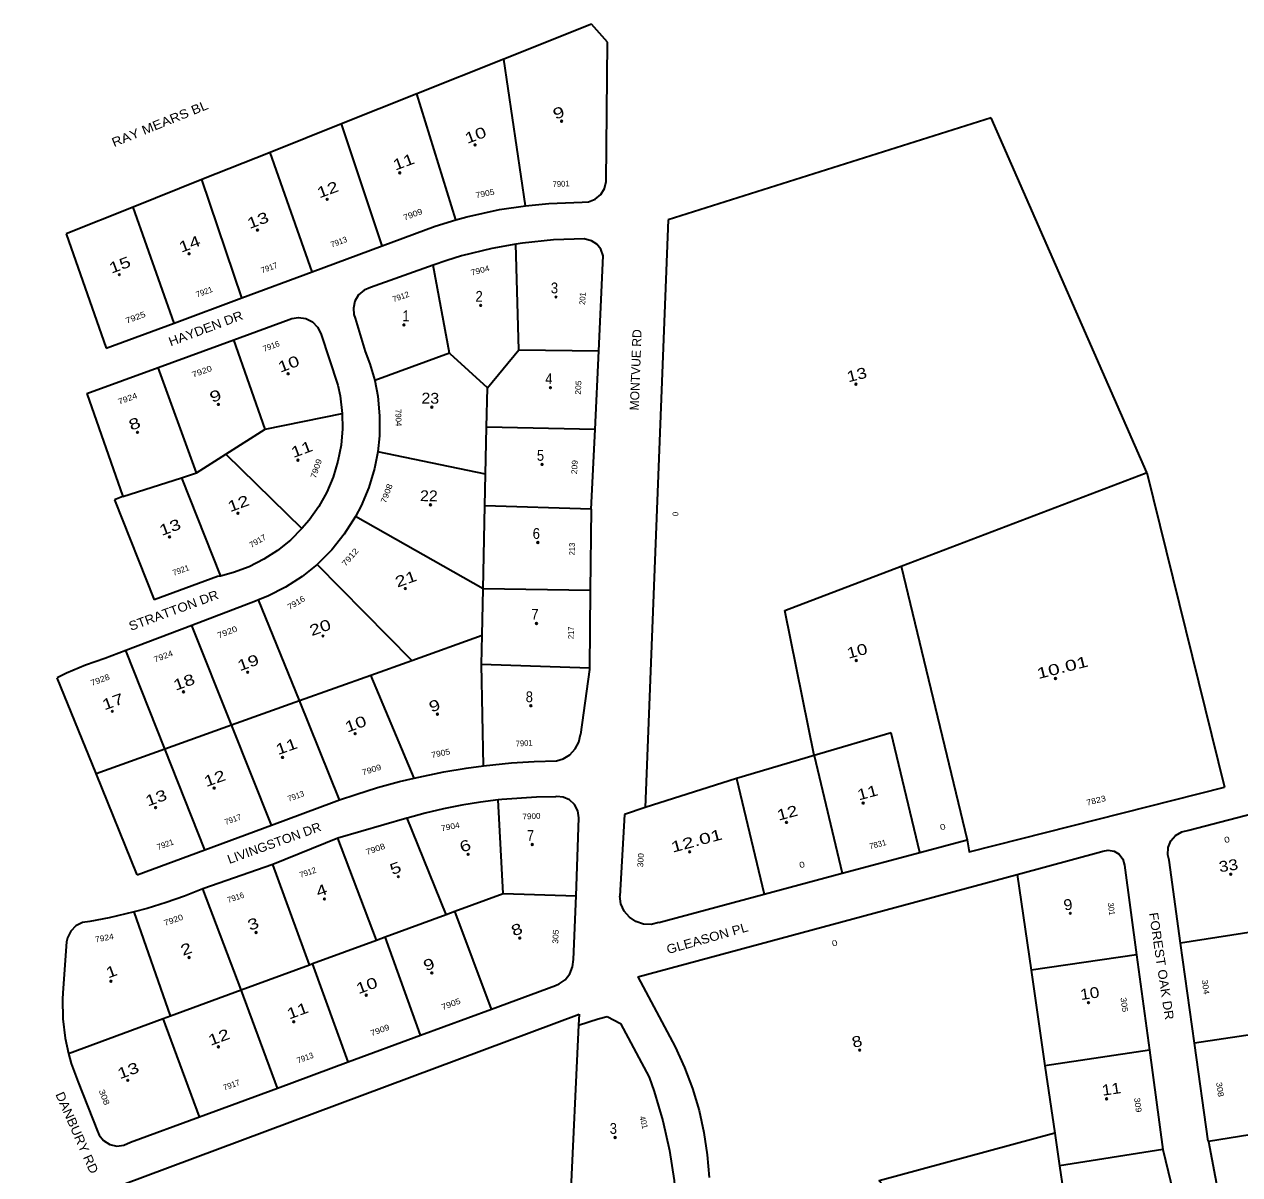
# Model space of a CAD drawing. Extents: x 2546959 to 2550387, y 581906 to 585027.
# Drawn here: x 2547419 to 2549102, y 583434 to 585027 of the extents above; entities that cross this region are included whole.
import ezdxf
from ezdxf.enums import TextEntityAlignment as Align

# ---------------------------------------------------------------- set-up
doc = ezdxf.new("R2010")
doc.units = 0
doc.header["$LTSCALE"] = 5
doc.header["$PDMODE"] = 32
doc.header["$PDSIZE"] = 2.5
for name, color, linetype in [('20', 7, 'Continuous'), ('38', 7, 'Continuous'), ('39', 7, 'Continuous'), ('41', 7, 'Continuous')]:
    doc.layers.add(name, color=color, linetype=linetype)
doc.layers.add('40', color=7, linetype='Continuous', lineweight=35)

msp = doc.modelspace()

# ---------------------------------------------------------------- linework, layer by layer
at = {"layer": '40'}
for p, q in [((2548204.014, 585026.501), (2548082.739, 584978.146)), ((2548226.245, 585001.697), (2548204.014, 585026.501)), ((2548224.277, 584808.852), (2548226.245, 585001.697)), ((2548082.739, 584978.146), (2547962.303, 584930.126)), ((2548112.924, 584775.333), (2548082.739, 584978.146)), ((2547962.303, 584930.126), (2547858.204, 584888.62)), ((2548016.151, 584755.782), (2547962.303, 584930.126)), ((2547858.204, 584888.62), (2547759.114, 584849.112)), ((2547914.388, 584719.889), (2547858.204, 584888.62)), ((2548757.466, 584896.871), (2548310.336, 584755.908)), ((2548972.954, 584405.881), (2548757.466, 584896.871)), ((2547759.114, 584849.112), (2547664.568, 584811.416)), ((2547817.297, 584683.807), (2547759.114, 584849.112)), ((2547664.568, 584811.416), (2547569.517, 584773.517)), ((2547720.206, 584647.727), (2547664.568, 584811.416)), ((2547569.517, 584773.517), (2547476.689, 584736.505)), ((2547626.39, 584612.862), (2547569.517, 584773.517)), ((2547987.542, 584747.075), (2548016.151, 584755.782)), ((2548310.336, 584755.908), (2548278.336, 583942.322)), ((2547476.689, 584736.505), (2547532.448, 584577.95)), ((2547914.388, 584719.889), (2547987.542, 584747.075)), ((2547817.297, 584683.807), (2547914.388, 584719.889)), ((2548103.512, 584576.042), (2548099.538, 584722.294)), ((2548003.755, 584699.71), (2547984.922, 584692.969)), ((2548214.27, 584574.238), (2548220.537, 584706.084)), ((2547720.206, 584647.727), (2547817.297, 584683.807)), ((2547984.922, 584692.969), (2547898.412, 584662.004)), ((2548007.585, 584570.978), (2547984.922, 584692.969)), ((2547626.39, 584612.862), (2547720.206, 584647.727)), ((2547709.072, 584589.763), (2547785.46, 584617.652)), ((2547532.448, 584577.95), (2547626.39, 584612.862)), ((2547829.533, 584598.297), (2547852.84, 584526.961)), ((2547752.252, 584465.989), (2547709.072, 584589.763)), ((2548007.585, 584570.978), (2547904.091, 584533.141)), ((2548008.322, 584570.311), (2548007.585, 584570.978)), ((2548060.181, 584523.422), (2548008.322, 584570.311)), ((2548060.181, 584523.422), (2548103.512, 584576.042)), ((2548103.512, 584576.042), (2548214.27, 584574.238)), ((2548209.112, 584465.708), (2548214.27, 584574.238)), ((2547505.384, 584515.396), (2547604.222, 584551.482)), ((2547505.384, 584515.396), (2547555.274, 584372.68)), ((2547697.97, 584431.3), (2547752.252, 584465.989)), ((2548209.112, 584465.708), (2548059.011, 584468.839)), ((2548203.861, 584355.253), (2548209.112, 584465.708)), ((2547657.54, 584405.464), (2547697.97, 584431.3)), ((2547697.97, 584431.3), (2547803.347, 584328.288)), ((2548057.619, 584403.911), (2547908.224, 584434.685)), ((2547636.483, 584398.714), (2547657.54, 584405.464)), ((2547636.483, 584398.714), (2547690.507, 584262.679)), ((2548632.906, 584276.263), (2548972.05, 584405.537)), ((2547555.553, 584372.77), (2547543.687, 584368.085)), ((2547543.687, 584368.085), (2547598.762, 584229.478)), ((2548054.214, 584245.13), (2547877.415, 584344.957)), ((2548203.861, 584355.253), (2548202.493, 584242.777)), ((2547955.225, 584145.719), (2547824.237, 584278.814)), ((2547686.611, 584261.811), (2547598.762, 584229.478)), ((2547690.507, 584262.679), (2547686.611, 584261.811)), ((2548471.7, 584214.815), (2548632.906, 584276.263)), ((2548632.906, 584276.263), (2548724.329, 583897.607)), ((2548052.831, 584180.633), (2548054.214, 584245.13)), ((2547739.134, 584227.906), (2547650.734, 584194.276)), ((2547743.36, 584229.523), (2547739.134, 584227.906)), ((2547799.804, 584090.124), (2547743.36, 584229.523)), ((2548202.493, 584242.777), (2548201.181, 584134.88)), ((2548512.325, 584014.19), (2548471.7, 584214.815)), ((2547650.734, 584194.276), (2547559.711, 584159.647)), ((2547705.757, 584056.483), (2547650.734, 584194.276)), ((2547955.225, 584145.719), (2548052.831, 584180.633)), ((2548051.967, 584140.339), (2548052.831, 584180.633)), ((2547559.711, 584159.647), (2547530.552, 584148.553)), ((2547613.638, 584023.531), (2547559.711, 584159.647)), ((2548054.645, 584000.017), (2548051.866, 584140.342)), ((2548051.967, 584140.339), (2548051.866, 584140.342)), ((2548201.181, 584134.88), (2548051.967, 584140.339)), ((2548201.161, 584133.322), (2548189.038, 584043.393)), ((2548201.181, 584134.88), (2548201.161, 584133.322)), ((2547518.285, 583989.423), (2547464.644, 584121.761)), ((2548658.645, 583879.97), (2548619.071, 584045.736)), ((2547668.847, 583883.672), (2547613.66, 584023.54)), ((2548512.325, 584014.19), (2548405.115, 583982.508)), ((2548405.115, 583982.508), (2548278.336, 583942.322)), ((2548405.115, 583982.508), (2548443.168, 583822.113)), ((2547761.113, 583917.857), (2547847.926, 583950.022)), ((2547847.926, 583950.022), (2547855.466, 583952.653)), ((2548081.692, 583823.179), (2548075.091, 583952.616)), ((2548278.336, 583942.322), (2548249.659, 583932.695)), ((2547948.711, 583927.52), (2547853.11, 583899.636)), ((2547948.836, 583927.554), (2547948.711, 583927.52)), ((2548002.792, 583794.151), (2547948.836, 583927.554)), ((2548182.892, 583820.016), (2548186.775, 583928.069)), ((2548249.659, 583932.695), (2548243.372, 583819.636)), ((2549031.214, 583910.794), (2549145.332, 583940.621)), ((2547668.847, 583883.672), (2547761.113, 583917.857)), ((2547853.11, 583899.636), (2547763.012, 583863.08)), ((2547906.568, 583758.75), (2547853.11, 583899.636)), ((2548658.645, 583879.97), (2548724.329, 583897.607)), ((2547575.211, 583848.979), (2547668.847, 583883.672)), ((2548551.317, 583851.152), (2548658.645, 583879.97)), ((2548793.282, 583849.522), (2548910.499, 583881.177)), ((2547763.012, 583863.08), (2547666.276, 583829.512)), ((2547813.679, 583724.576), (2547763.012, 583863.08)), ((2549019.704, 583754.571), (2549003.678, 583869.22)), ((2548268.244, 583707.733), (2548793.282, 583849.522)), ((2548443.168, 583822.113), (2548551.317, 583851.152)), ((2548793.282, 583849.522), (2548812.656, 583716.826)), ((2547718.94, 583689.721), (2547666.276, 583829.512)), ((2548014.971, 583798.632), (2548081.692, 583823.179)), ((2548081.692, 583823.179), (2548182.892, 583820.016)), ((2548179.03, 583731.77), (2548182.892, 583820.016)), ((2548297.603, 583782.942), (2548443.168, 583822.113)), ((2547621.476, 583653.864), (2547571.179, 583797.638)), ((2548002.792, 583794.151), (2548014.971, 583798.632)), ((2548065.549, 583663.105), (2548014.971, 583798.632)), ((2549192.015, 583780.951), (2549019.704, 583754.571)), ((2547477.488, 583756.191), (2547472.221, 583685.75)), ((2547906.568, 583758.75), (2547918.458, 583763.125)), ((2549039.085, 583615.922), (2549019.704, 583754.571)), ((2547718.94, 583689.721), (2547813.679, 583724.576)), ((2547813.679, 583724.576), (2547817.869, 583726.118)), ((2548268.244, 583707.733), (2548319.879, 583611.016)), ((2547621.476, 583653.864), (2547718.94, 583689.721)), ((2547769.401, 583553.845), (2547718.94, 583689.721)), ((2548065.549, 583663.105), (2548154.407, 583695.887)), ((2547418.933, 583369.569), (2548187.133, 583655.923)), ((2547967.597, 583626.967), (2548065.549, 583663.105)), ((2547479.989, 583601.811), (2547611.293, 583650.118)), ((2548186.209, 583640.677), (2548173.506, 583374.598)), ((2548213.399, 583649.463), (2548225.941, 583652.934)), ((2548225.941, 583652.934), (2548244.139, 583643.253)), ((2548244.139, 583643.253), (2548284.022, 583568.754)), ((2549231.828, 583644.78), (2549039.085, 583615.922)), ((2547867.433, 583590.013), (2547967.597, 583626.967)), ((2548976.581, 583606.27), (2548995.202, 583468.491)), ((2549058.078, 583480.042), (2549039.085, 583615.922)), ((2547769.401, 583553.845), (2547867.433, 583590.013)), ((2547493.52, 583562.139), (2547520.143, 583494.249)), ((2547661.372, 583513.99), (2547769.401, 583553.845)), ((2547565.755, 583478.713), (2547661.372, 583513.99)), ((2549058.078, 583480.042), (2549058.121, 583479.818)), ((2548995.202, 583468.491), (2548852.159, 583446.26)), ((2548995.202, 583468.491), (2549016.87, 583378.193))]:
    msp.add_line(p, q, dxfattribs=at)
for points in [[(2548191.184, 584780.398), (2548200.115, 584780.809), (2548209.399, 584784.32), (2548217.032, 584790.665), (2548222.178, 584799.151), (2548224.277, 584808.852)], [(2548016.151, 584755.782), (2548031.713, 584760.06), (2548076.691, 584769.891), (2548112.924, 584775.333)], [(2548112.924, 584775.333), (2548145.178, 584778.626), (2548191.184, 584780.398)], [(2548099.538, 584722.294), (2548066.18, 584716.339), (2548024.363, 584705.988), (2548003.755, 584699.71)], [(2548194.544, 584729.359), (2548151.485, 584728.054), (2548108.625, 584723.707), (2548099.538, 584722.294)], [(2548220.537, 584706.084), (2548217.082, 584715.276), (2548211.48, 584722.12), (2548204.06, 584726.936), (2548195.544, 584729.191), (2548194.544, 584729.359)], [(2547898.412, 584662.004), (2547889.229, 584658.263), (2547881.71, 584651.797), (2547876.634, 584643.278), (2547874.528, 584633.588), (2547875.333, 584624.802), (2547877.097, 584619.566), (2547891.035, 584573.532)], [(2547785.46, 584617.652), (2547789.21, 584619.054), (2547798.645, 584620.715), (2547808.722, 584619.231), (2547817.816, 584614.642), (2547824.998, 584607.418), (2547829.533, 584598.297)], [(2547657.54, 584405.464), (2547604.222, 584551.482), (2547709.072, 584589.763)], [(2547891.035, 584573.532), (2547897.495, 584556.359), (2547904.091, 584533.141)], [(2547904.091, 584533.141), (2547908.238, 584511.815), (2547910.874, 584484.426), (2547910.612, 584456.912), (2547908.224, 584434.685)], [(2547852.84, 584526.961), (2547856.068, 584512.098), (2547859.021, 584487.888)], [(2548203.861, 584355.253), (2548056.679, 584360.068), (2548057.619, 584403.911), (2548059.011, 584468.839), (2548060.181, 584523.422)], [(2547752.252, 584465.989), (2547752.479, 584466.134), (2547859.021, 584487.888)], [(2547859.021, 584487.888), (2547859.399, 584466.668), (2547857.459, 584443.942), (2547853.138, 584421.547), (2547846.481, 584399.732), (2547837.564, 584378.739), (2547826.485, 584358.802), (2547813.367, 584340.144), (2547803.347, 584328.288)], [(2547908.224, 584434.685), (2547903.752, 584411.608), (2547895.859, 584385.249), (2547885.232, 584359.868), (2547877.415, 584344.957)], [(2547555.274, 584372.68), (2547555.553, 584372.77), (2547636.483, 584398.714)], [(2548972.05, 584405.537), (2548972.954, 584405.881), (2549080.399, 583970.174)], [(2547877.415, 584344.957), (2547861.784, 584320.502), (2547844.527, 584299.07), (2547824.237, 584278.814)], [(2548202.493, 584242.777), (2548054.214, 584245.13), (2548056.679, 584360.068)], [(2547803.347, 584328.288), (2547787.382, 584312.442), (2547769.599, 584298.159), (2547750.411, 584285.83), (2547730.03, 584275.59), (2547708.684, 584267.554), (2547690.507, 584262.679)], [(2547824.237, 584278.814), (2547803.746, 584262.235), (2547780.676, 584247.241), (2547756.154, 584234.761), (2547743.36, 584229.523)], [(2547530.552, 584148.553), (2547503.636, 584139.218), (2547477.436, 584128.032), (2547464.644, 584121.761)], [(2547958.685, 583982.997), (2547898.743, 584125.514), (2547955.225, 584145.719)], [(2547855.466, 583952.653), (2547799.804, 584090.124), (2547898.743, 584125.514)], [(2547761.113, 583917.857), (2547705.757, 584056.483), (2547799.804, 584090.124)], [(2547613.638, 584023.531), (2547613.66, 584023.54), (2547705.757, 584056.483)], [(2548155.677, 584006.992), (2548164.796, 584009.704), (2548174.102, 584015.309), (2548181.577, 584023.194), (2548186.68, 584032.787), (2548189.038, 584043.393)], [(2548619.071, 584045.736), (2548512.325, 584014.19), (2548551.317, 583851.152)], [(2547575.211, 583848.979), (2547518.285, 583989.423), (2547613.638, 584023.531)], [(2547958.685, 583982.997), (2547999.751, 583991.67), (2548030.843, 583996.867), (2548054.645, 584000.017)], [(2548054.645, 584000.017), (2548093.467, 584004.073), (2548124.926, 584006.073), (2548155.677, 584006.992)], [(2547855.466, 583952.653), (2547877.689, 583960.409), (2547907.788, 583969.778), (2547938.188, 583978.118), (2547958.685, 583982.997)], [(2548724.329, 583897.607), (2548726.889, 583880.611), (2549080.399, 583970.174)], [(2548075.091, 583952.616), (2548050.377, 583949.486), (2548024.689, 583945.323), (2547999.162, 583940.271), (2547973.825, 583934.333), (2547948.836, 583927.554)], [(2548154.105, 583957.155), (2548128.089, 583956.591), (2548080.091, 583953.111), (2548075.091, 583952.616)], [(2548186.775, 583928.069), (2548185.364, 583937.675), (2548180.829, 583946.259), (2548173.688, 583952.838), (2548164.762, 583956.655), (2548156.105, 583957.261), (2548154.105, 583957.155)], [(2549003.678, 583869.22), (2549001.94, 583876.807), (2549002.568, 583886.777), (2549006.338, 583896.027), (2549012.857, 583903.596), (2549021.447, 583908.695), (2549031.214, 583910.794)], [(2548910.499, 583881.177), (2548912.166, 583881.737), (2548919.412, 583883.309), (2548927.705, 583881.91), (2548934.869, 583877.503), (2548939.857, 583870.73), (2548941.941, 583862.582)], [(2548941.941, 583862.582), (2548958.719, 583738.442), (2548976.581, 583606.27)], [(2547666.276, 583829.512), (2547640.921, 583819.526), (2547615.206, 583810.504), (2547589.169, 583802.46), (2547571.179, 583797.638)], [(2548297.603, 583782.942), (2548286.951, 583780.42), (2548276.014, 583780.894), (2548265.62, 583784.329), (2548256.554, 583790.463), (2548249.501, 583798.834), (2548244.993, 583808.81), (2548243.372, 583819.636)], [(2547571.179, 583797.638), (2547536.277, 583789.348), (2547509.499, 583784.299)], [(2547967.597, 583626.967), (2547918.458, 583763.125), (2548002.792, 583794.151)], [(2547509.499, 583784.299), (2547499.408, 583782.797), (2547490.312, 583778.176), (2547483.147, 583770.913), (2547478.651, 583761.756), (2547477.488, 583756.191)], [(2547867.433, 583590.013), (2547817.869, 583726.118), (2547906.568, 583758.75)], [(2548154.407, 583695.887), (2548159.407, 583697.982), (2548167.687, 583703.792), (2548174.141, 583711.881), (2548178.029, 583721.471), (2548179.03, 583731.77)], [(2548958.719, 583738.442), (2548812.656, 583716.826), (2548831.943, 583584.719)], [(2547472.221, 583685.75), (2547471.769, 583676.718), (2547472.253, 583649.6), (2547475.491, 583622.673), (2547479.989, 583601.811)], [(2548187.133, 583655.923), (2548186.209, 583640.677), (2548213.399, 583649.463)], [(2547661.372, 583513.99), (2547611.293, 583650.118), (2547621.476, 583653.864)], [(2548319.879, 583611.016), (2548332.974, 583582.446), (2548344.033, 583553.027), (2548353, 583522.905), (2548359.831, 583492.227), (2548364.494, 583461.146), (2548366.966, 583429.815)], [(2548976.581, 583606.27), (2548831.943, 583584.719), (2548845.598, 583491.199)], [(2547479.989, 583601.811), (2547484.033, 583587.548), (2547493.52, 583562.139)], [(2548284.022, 583568.754), (2548290.963, 583548.887), (2548302.841, 583508.518), (2548312.007, 583467.447), (2548318.419, 583425.856), (2548322.049, 583383.932)], [(2549270.052, 583514.047), (2549058.121, 583479.818), (2549081.302, 583357.597), (2549259.719, 583385.325)], [(2547520.143, 583494.249), (2547522.524, 583488.757), (2547528.747, 583480.995), (2547537.166, 583475.698), (2547546.855, 583473.446), (2547556.749, 583474.49), (2547565.755, 583478.713)], [(2548845.598, 583491.199), (2548602.241, 583425.464), (2548680.492, 583339.561)], [(2548845.598, 583491.199), (2548852.159, 583446.26), (2548862.168, 583377.706)]]:
    msp.add_lwpolyline(points, dxfattribs=at)
at = {"layer": '41'}
for p in [(2548162.752, 584892.32), (2548043.004, 584859.485), (2547938.708, 584820.856), (2547838.274, 584784.159), (2547741.704, 584741.667), (2547647.064, 584708.833), (2547550.494, 584679.862), (2548155.025, 584648.96), (2548050.729, 584637.372), (2547944.501, 584610.332), (2547784.194, 584542.731), (2548147.299, 584523.418), (2548570.278, 584528.246), (2547687.623, 584500.24), (2547983.129, 584496.378), (2547575.601, 584461.611), (2547797.714, 584422.983), (2548135.71, 584417.19), (2547981.197, 584361.178), (2547714.663, 584349.588), (2547620.023, 584316.754), (2548129.916, 584309.03), (2547946.432, 584245.293), (2548127.984, 584197.008), (2547832.478, 584179.624), (2548570.661, 584145.703), (2547728.182, 584129.406), (2548846.468, 584120.717), (2547639.337, 584102.366), (2547540.835, 584075.326), (2548120.258, 584083.054), (2547990.854, 584071.464), (2547876.9, 584044.424), (2547776.467, 584011.59), (2547681.827, 583969.099), (2547600.708, 583942.059), (2548580.312, 583948.378), (2548474.143, 583921.567), (2548122.189, 583890.878), (2548033.343, 583877.358), (2548340.092, 583880.814), (2547936.773, 583846.455), (2549089.131, 583849.719), (2547834.408, 583815.552), (2548867.019, 583795.638), (2547739.768, 583769.197), (2548104.805, 583761.473), (2547647.06, 583734.432), (2547983.126, 583713.187), (2547538.902, 583701.597), (2547892.35, 583682.284), (2548892.127, 583672.028), (2547791.916, 583645.586), (2547687.62, 583610.82), (2548575.376, 583606.359), (2547562.078, 583564.466), (2548917.235, 583538.76), (2548236.848, 583485.331)]:
    msp.add_point(p, dxfattribs=at)

# ---------------------------------------------------------------- texts
at = {"layer": '20'}
for s, rotation, width, p in [('RAY MEARS BL', 22.079, 1.15, (2547608.953, 584883.111)), ('HAYDEN DR', 20.548, 1.1, (2547672.257, 584599.551)), ('STRATTON DR', 20.187, 1.1, (2547627.783, 584209.234)), ('LIVINGSTON DR', 19.906, 1.05, (2547767.029, 583887.177)), ('FOREST OAK DR', 278.597, 1.1, (2548987.115, 583721.671)), ('GLEASON PL', 15.913, 1.1, (2548366.146, 583755.161)), ('DANBURY RD', 293.728, 1.1, (2547486.187, 583489.47))]:
    msp.add_text(s, height=12.5, rotation=rotation, dxfattribs=dict(at, width=width)).set_placement(p, align=Align.CENTER)
msp.add_text('MONTVUE RD', height=12.5, rotation=87.974, dxfattribs=at).set_placement((2548271.586, 584547.885), align=Align.CENTER)
at = {"layer": '38'}
for s, rotation, width, p in [('9', 20.386, 1.4, (2548161.296, 584897.085)), ('10', 20.386, 1.35, (2548046.161, 584866.066)), ('11', 20.386, 1.35, (2547946.545, 584829.075)), ('12', 20.386, 1.35, (2547841.47, 584790.653)), ('13', 20.386, 1.35, (2547744.885, 584748.2)), ('14', 20.386, 1.35, (2547650.22, 584715.347)), ('15', 20.386, 1.35, (2547553.688, 584686.44)), ('3', 359.091, 0.9, (2548152.769, 584653.988)), ('2', 359.091, 0.9, (2548048.45, 584642.361)), ('1', 359.091, 0.9, (2547947.172, 584615.296)), ('10', 20.386, 1.35, (2547787.39, 584549.269)), ('13', 14.217, 1.25, (2548573.277, 584534.191)), ('4', 359.091, 0.9, (2548145.035, 584528.443)), ('9', 20.386, 1.4, (2547686.155, 584505.088)), ('23', 359.091, 1.1, (2547980.878, 584501.35)), ('8', 20.386, 1.4, (2547574.103, 584466.474)), ('11', 20.386, 1.35, (2547805.532, 584431.211)), ('5', 359.091, 0.9, (2548133.462, 584422.204)), ('22', 359.091, 1.1, (2547978.957, 584366.204)), ('12', 20.386, 1.35, (2547717.844, 584356.097)), ('13', 20.386, 1.35, (2547623.179, 584323.244)), ('6', 359.091, 0.9, (2548127.648, 584314.045)), ('21', 19.682, 1.35, (2547949.625, 584251.651)), ('7', 359.091, 0.9, (2548125.728, 584202.046)), ('20', 19.682, 1.35, (2547830.982, 584184.38)), ('10', 15.03, 1.3, (2548573.686, 584151.698)), ('19', 19.682, 1.35, (2547731.334, 584135.811)), ('10.01', 14.217, 1.45, (2548857.843, 584128.848)), ('18', 19.682, 1.35, (2547642.536, 584108.825)), ('17', 19.682, 1.35, (2547544.031, 584081.731)), ('8', 359.091, 0.9, (2548117.994, 584088.02)), ('9', 19.682, 1.35, (2547989.379, 584076.222)), ('10', 19.682, 1.35, (2547880.079, 584050.799)), ('11', 19.682, 1.35, (2547784.324, 584019.723)), ('12', 19.682, 1.35, (2547684.988, 583975.493)), ('13', 19.682, 1.35, (2547603.869, 583948.506)), ('11', 15.03, 1.3, (2548588.129, 583955.653)), ('12', 15.03, 1.3, (2548477.154, 583927.593)), ('12.01', 15.03, 1.45, (2548351.457, 583888.976)), ('6', 20.199, 1.35, (2548031.859, 583882.141)), ('5', 20.199, 1.35, (2547935.327, 583851.208)), ('33', 8.834, 1.2, (2549087.084, 583854.487)), ('4', 20.199, 1.35, (2547832.929, 583820.381)), ('9', 8.418, 1.1, (2548864.951, 583800.401)), ('3', 20.199, 1.35, (2547738.317, 583773.981)), ('8', 20.199, 1.35, (2548103.325, 583766.302)), ('2', 20.199, 1.35, (2547645.571, 583739.208)), ('1', 20.199, 1.35, (2547542.069, 583708.067)), ('9', 20.199, 1.35, (2547981.673, 583717.983)), ('10', 20.199, 1.35, (2547895.556, 583688.764)), ('10', 8.418, 1.2, (2548894.977, 583677.502)), ('11', 20.199, 1.35, (2547799.733, 583653.783)), ('12', 20.199, 1.35, (2547690.813, 583617.297)), ('8', 15.116, 1.25, (2548573.663, 583611.009)), ('13', 20.199, 1.35, (2547565.268, 583571.004)), ('11', 8.418, 1.2, (2548925.003, 583545.002))]:
    msp.add_text(s, height=15, rotation=rotation, dxfattribs=dict(at, width=width)).set_placement(p, align=Align.CENTER)
at = {"layer": '38', "width": 0.9}
for s, p in [('7', (2548119.708, 583895.878)), ('3', (2548234.368, 583490.331))]:
    msp.add_text(s, height=15, dxfattribs=at).set_placement(p, align=Align.CENTER)
at = {"layer": '39'}
for s, rotation, width, p in [('7901', 3.218, 0.9, (2548162.286, 584801.623)), ('7905', 11.318, 1.1, (2548057.568, 584788.457)), ('7909', 20.386, 1.15, (2547958.146, 584759.551)), ('7904', 14.917, 1.1, (2548050.963, 584681.966)), ('201', 87.279, 0.9, (2548195.683, 584646.653)), ('7925', 20.387, 1.2, (2547574.257, 584616.937)), ('7920', 20.057, 1.2, (2547666.159, 584542.14)), ('205', 87.279, 1.1, (2548189.811, 584523.318)), ('7924', 20.057, 1.15, (2547563.281, 584504.594)), ('7909', 71.017, 1.15, (2547826.789, 584410.146)), ('209', 87.279, 1.1, (2548184.585, 584413.24)), ('7908', 69.293, 1.15, (2547924.274, 584375.587)), ('7917', 30.71, 1.05, (2547744.054, 584307.711)), ('7912', 49.143, 1.2, (2547873.001, 584286.096)), ('213', 89.303, 0.95, (2548181.137, 584300.02)), ('7916', 31.003, 1.1, (2547797.322, 584222.189)), ('7920', 20.829, 1.2, (2547701.299, 584181.35)), ('217', 89.303, 0.85, (2548179.751, 584183.968)), ('7924', 20.829, 1.15, (2547612.767, 584147.75)), ('7928', 20.125, 1.15, (2547525.209, 584115.163)), ('7901', 3.638, 0.9, (2548111.197, 584027.229)), ('7905', 11.44, 1.1, (2547996.197, 584013.43)), ('7909', 17.29, 1.15, (2547900.881, 583990.701)), ('7823', 14.217, 1.15, (2548903.6, 583948.07)), ('7900', 3.231, 1.05, (2548121.298, 583926.17)), ('7904', 11.196, 1.1, (2548009.548, 583911.767)), ('0', 15.03, 1.3, (2548691.447, 583911.528)), ('7908', 19.138, 1.15, (2547906.3, 583880.96)), ('0', 14.648, 1.3, (2549084.935, 583893.801)), ('300', 86.817, 1.1, (2548276.103, 583869.032)), ('0', 15.03, 1.3, (2548496.623, 583859.155)), ('301', 277.697, 0.95, (2548919.95, 583801.259)), ('7920', 19.333, 1.15, (2547626.756, 583782.735)), ('7924', 10.678, 1.1, (2547530.497, 583757.72)), ('305', 87.494, 1.1, (2548158.395, 583763.22)), ('0', 15.113, 1.3, (2548541.859, 583750.574)), ('304', 277.958, 1.15, (2549050.494, 583693.208)), ('7905', 20.251, 1.15, (2548010.923, 583666.431)), ('305', 277.697, 1.15, (2548937.901, 583668.602)), ('7909', 20.251, 1.15, (2547912.579, 583630.165)), ('308', 277.957, 1.15, (2549070.334, 583551.235)), ('308', 291.412, 1.25, (2547525.971, 583539.711)), ('309', 277.697, 1.15, (2548956.675, 583529.832))]:
    msp.add_text(s, height=8, rotation=rotation, dxfattribs=dict(at, width=width)).set_placement(p, align=Align.CENTER)
for s, rotation, p in [('7913', 20.386, (2547855.743, 584721.49)), ('7917', 20.386, (2547759.371, 584685.756)), ('7921', 20.386, (2547669.442, 584652.309)), ('7912', 19.694, (2547941.455, 584645.626)), ('7916', 20.057, (2547762.043, 584577.16)), ('7904', 271.467, (2547932.962, 584481.833)), ('0', 87.748, (2548324.368, 584348.388)), ('7921', 20.206, (2547636.99, 584267.022)), ('7913', 20.33, (2547796.214, 583954.242)), ('7917', 20.33, (2547709.014, 583921.922)), ('7921', 20.33, (2547615.459, 583887.299)), ('7831', 15.03, (2548601.537, 583887.365)), ('7912', 19.137, (2547812.732, 583848.495)), ('7916', 19.137, (2547712.84, 583813.829)), ('7913', 20.251, (2547809.053, 583591.896)), ('7917', 20.251, (2547707.19, 583554.35)), ('401', 285.442, (2548272.632, 583505.239))]:
    msp.add_text(s, height=8, rotation=rotation, dxfattribs=at).set_placement(p, align=Align.CENTER)

doc.saveas('drawing.dxf')
